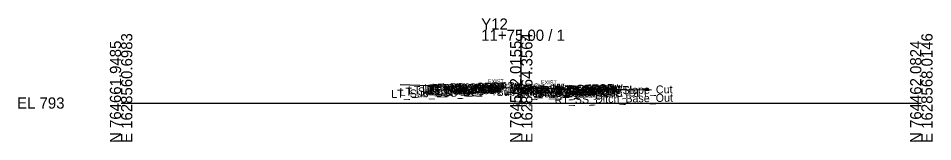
# Model space of a CAD drawing. Extents: x -26 to 203, y -10 to 3521.
# Drawn here: x -25.7 to 202.8, y 3490.3 to 3521.2 of the extents above; entities that cross this region are included whole.
import ezdxf

# ---------------------------------------------------------------- set-up
doc = ezdxf.new("R2010")
doc.units = 0
for name, color, linetype in [('Default', 7, 'Continuous'), ('Exist Cross Section Cell', 7, 'Continuous'), ('Exist XS Center Line Elevation Label', 7, 'Continuous'), ('Exist XS Ground Line', 7, 'Continuous'), ('Prop XS SE Text', 7, 'Continuous'), ('Scratch_Level_0', 7, 'Continuous')]:
    doc.layers.add(name, color=color, linetype=linetype)

msp = doc.modelspace()

# ---------------------------------------------------------------- linework, layer by layer
at = {"layer": 'Exist Cross Section Cell'}
for p, q in [((100, 3500), (100, 3518.37)), ((0, 3500), (100, 3500)), ((100, 3500), (200, 3500))]:
    msp.add_line(p, q, dxfattribs=at)
at = {"layer": 'Exist XS Ground Line'}
msp.add_lwpolyline([(69.73, 3504.66), (86.8, 3504.02), (94.35, 3503.88), (100, 3503.79), (113.3, 3503.57), (120.99, 3503.37), (126.39, 3503.37), (132.58, 3503.28)], dxfattribs=at)

# ---------------------------------------------------------------- texts
at = {"layer": 'Default'}
msp.add_text('-', height=0.0001, dxfattribs=at).set_placement((0, 3500))
at = {"layer": 'Exist Cross Section Cell'}
for s, p in [('Y12', (90, 3518.37)), ('11+75.00 / 1', (90, 3515.57)), ('EL 793', (-26, 3498.6))]:
    msp.add_text(s, height=2.8, dxfattribs=at).set_placement(p)
for s, p in [('E 1628560.6983', (2.8, 3490)), ('E 1628564.3564', (102.8, 3490)), ('E 1628568.0146', (202.8, 3490)), ('N 764661.9485', (0, 3490)), ('N 764562.0155', (100, 3490)), ('N 764462.0824', (200, 3490))]:
    msp.add_text(s, height=2.8, rotation=90, dxfattribs=at).set_placement(p)
at = {"layer": 'Exist XS Center Line Elevation Label'}
msp.add_text('796.79', height=1.2, dxfattribs=at).set_placement((97.56, 3499.19))
at = {"layer": 'Prop XS SE Text'}
for p in [(91.65, 3504.96), (104.9, 3504.69)]:
    msp.add_text('EXIST.', height=1, rotation=358.8542, dxfattribs=at).set_placement(p)
at = {"layer": 'Scratch_Level_0'}
for s, p in [('LT_Sub_OSS_DLT', (67.53, 3501.27)), ('LT_Sub_Trench_Out', (69.6, 3501.79)), ('LT_PS3_Shelf_Out', (71.72, 3502.17)), ('LT_PV2_OEEOP_W', (75.24, 3502.53)), ('LT_PV3_OEEOP_W', (75.24, 3502.2)), ('LT_PV1_OEEOP_W', (75.81, 3502.67)), ('LT_PS3_OEOP', (76.47, 3502.26)), ('LT_PS2_OEOP', (76.81, 3502.6)), ('LT_Sub_OEOT', (76.9, 3501.94)), ('LT_PV2_OEOT', (77, 3502.61)), ('LT_PV3_OEOT', (77, 3502.27)), ('LT_PV1_OEOT', (77.57, 3502.87)), ('LT_PS1_OEOP', (77.63, 3502.87)), ('LT_PV1_OEEOP', (77.7, 3502.83)), ('RT_PV1_PGL_W', (89.86, 3502.46)), ('LT_PV1_PGL_W', (89.91, 3502.46)), ('Sub_PGL', (93.83, 3501.75)), ('PV2_PGL', (93.93, 3502.42)), ('PV3_PGL', (93.93, 3502.09)), ('PV1_PGL', (94.49, 3502.68)), ('RT_Sub_Trench_Out', (98.92, 3501.26)), ('RT_PV2_OEEOP_W', (99.7, 3502.04)), ('RT_PV3_OEEOP_W', (99.7, 3501.71)), ('RT_PV1_OEEOP_W', (100.26, 3502.18)), ('RT_PS3_Shelf_Out', (100.36, 3501.64)), ('RT_PV1_OEEOP', (102.15, 3502.34)), ('RT_Sub_OEOT', (103.36, 3501.41)), ('RT_PV2_OEOT', (103.45, 3502.08)), ('RT_PV3_OEOT', (103.45, 3501.74)), ('RT_PS2_OEOP', (103.77, 3502.07)), ('RT_PV1_OEOT', (104.02, 3502.34)), ('RT_PS1_OEOP', (104.08, 3502.34)), ('RT_PS3_OEOP', (104.11, 3501.73)), ('RT_GS_OS_CTL', (107.65, 3501.91)), ('RT_Sub_OSS_DLT', (108.36, 3501.2)), ('RT_Slope_Cut', (120.29, 3502.1)), ('RT_SS_Ditch_Base_Out', (108.36, 3499.76))]:
    msp.add_text(s, height=2, rotation=1.1458, dxfattribs=at).set_placement(p)

doc.saveas('drawing.dxf')
